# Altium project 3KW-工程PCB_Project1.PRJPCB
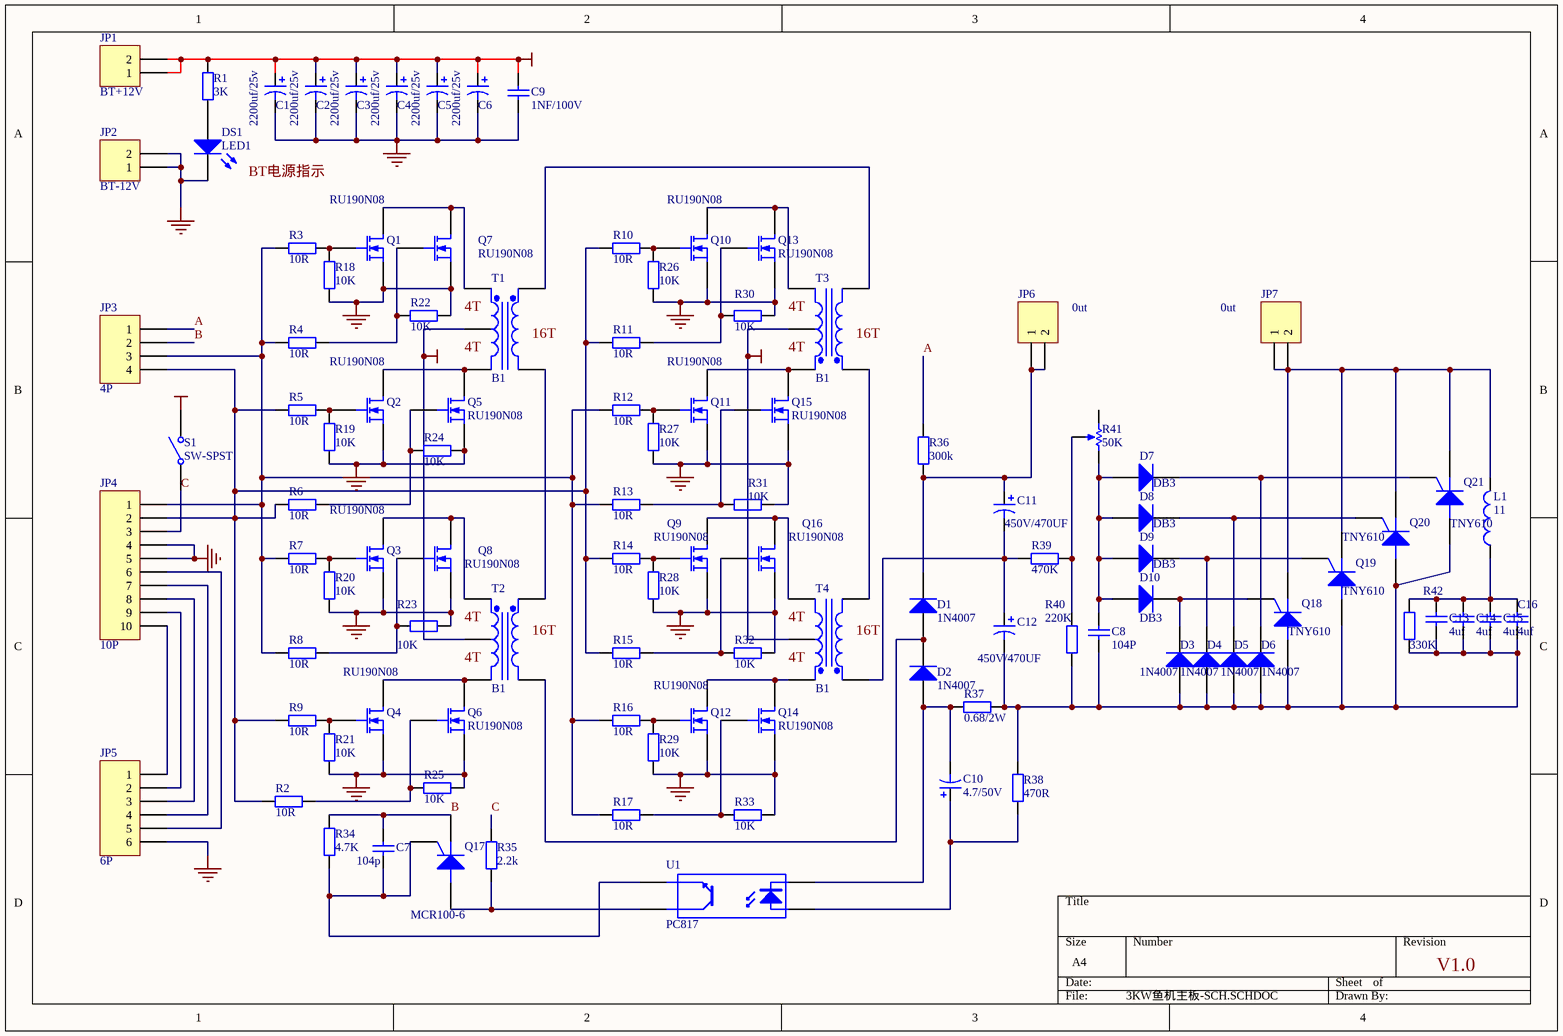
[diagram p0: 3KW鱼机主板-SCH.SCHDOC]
1 sheet, 104 parts. Net scope: global (net labels, ports and power ports of the same name join across sheets).

## Sheet 3KW鱼机主板-SCH.SCHDOC
size A4

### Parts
C1  2200uf/25v  [CAPPR5-5X5]
C2  2200uf/25v  [CAPPR5-5X5]
C3  2200uf/25v  [CAPPR5-5X5]
C4  2200uf/25v  [CAPPR5-5X5]
C5  2200uf/25v  [CAPPR5-5X5]
C6  2200uf/25v  [CAPPR5-5X5]
C7  104p  [RAD-0.3]
C8  104P  [RAD-0.3]
C9  1NF/100V  [RAD-0.1]
C10  4.7/50V  [CD5]
C11  450V/470UF  [450V/470UF]
C12  450V/470UF  [450V/470UF]
C13  4uf  [450v/3.5uf]
C14  4uf  [450v/3.5uf]
C15  4uf  [450v/3.5uf]
C16  4uf  [450v/3.5uf]
D1  1N4007  [DIO10.46-5.3x2.8]
D2  1N4007  [DIO10.46-5.3x2.8]
D3  1N4007  [DIO10.46-5.3x2.8]
D4  1N4007  [DIO10.46-5.3x2.8]
D5  1N4007  [DIO10.46-5.3x2.8]
D6  1N4007  [DIO10.46-5.3x2.8]
D7  DB3  [DIO7.8-4.6x2]
D8  DB3  [DIO7.8-4.6x2]
D9  DB3  [DIO7.8-4.6x2]
D10  DB3  [DIO7.8-4.6x2]
DS1  LED1  [BAT-2]
JP1  BT+12V  [HDR1X2]
JP2  BT-12V  [HDR1X2]
JP3  4P  [HDR1X4]
JP4  10P  [HDR1X10]
JP5  6P  [HDR1X6]
JP6  0ut  [HDR1X2]
JP7  0ut  [HDR1X2]
L1  11  [EC40]
Q1  RU190N08  [TO-220X]
Q2  RU190N08  [TO-220X]
Q3  RU190N08  [TO-220X]
Q4  RU190N08  [TO-220X]
Q5  RU190N08  [TO-220X]
Q6  RU190N08  [TO-220X]
Q7  RU190N08  [TO-220X]
Q8  RU190N08  [TO-220X]
Q9  RU190N08  [TO-220X]
Q10  RU190N08  [TO-220X]
Q11  RU190N08  [TO-220X]
Q12  RU190N08  [TO-220X]
Q13  RU190N08  [TO-220X]
Q14  RU190N08  [TO-220X]
Q15  RU190N08  [TO-220X]
Q16  RU190N08  [TO-220X]
Q17  MCR100-6  [BCY-W3/E4]
Q18  TNY610  [SFM-T3/E10.7V]
Q19  TNY610  [SFM-T3/E10.7V]
Q20  TNY610  [SFM-T3/E10.7V]
Q21  TNY610  [SFM-T3/E10.7V]
R1  3K  [AXIAL-0.4]
R2  10R  [AXIAL-0.4]
R3  10R  [AXIAL-0.4]
R4  10R  [AXIAL-0.4]
R5  10R  [AXIAL-0.4]
R6  10R  [AXIAL-0.4]
R7  10R  [AXIAL-0.4]
R8  10R  [AXIAL-0.4]
R9  10R  [AXIAL-0.4]
R10  10R  [AXIAL-0.4]
R11  10R  [AXIAL-0.4]
R12  10R  [AXIAL-0.4]
R13  10R  [AXIAL-0.4]
R14  10R  [AXIAL-0.4]
R15  10R  [AXIAL-0.4]
R16  10R  [AXIAL-0.4]
R17  10R  [AXIAL-0.4]
R18  10K  [AXIAL-0.4]
R19  10K  [AXIAL-0.4]
R20  10K  [AXIAL-0.4]
R21  10K  [AXIAL-0.4]
R22  10K  [AXIAL-0.4]
R23  10K  [AXIAL-0.4]
R24  10K  [AXIAL-0.4]
R25  10K  [AXIAL-0.4]
R26  10K  [AXIAL-0.4]
R27  10K  [AXIAL-0.4]
R28  10K  [AXIAL-0.4]
R29  10K  [AXIAL-0.4]
R30  10K  [AXIAL-0.4]
R31  10K  [AXIAL-0.4]
R32  10K  [AXIAL-0.4]
R33  10K  [AXIAL-0.4]
R34  4.7K  [AXIAL-0.4]
R35  2.2k  [AXIAL-0.4]
R36  300k  [AXIAL-0.4]
R37  0.68/2W  [AXIAL-0.4]
R38  470R  [AXIAL-0.4]
R39  470K  [AXIAL-0.4]
R40  220K  [AXIAL-0.4]
R41  50K  [VR5]
R42  330K  [AXIAL-0.5]
S1  SW-SPST  [SPST-2]
T1  B1  [EC40]
T2  B1  [EC40]
T3  B1  [EC40]
T4  B1  [EC40]
U1  PC817  [DIP-4]

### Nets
+12V: C1.1 C2.1 C3.1 C4.1 C5.1 C6.1 C9.2 JP1.1 JP1.2 R1.2 S1.2(NO) T1.4(SecCT) T2.4(SecCT) T3.4(SecCT) T4.4(SecCT)
GND: C1.2 C2.2 C3.2 C4.2 C5.2 C6.2 C9.1 DS1.2(K) JP2.1 JP2.2 JP4.4 JP4.5 JP5.6 Q1.3(S) Q2.3(S) Q3.3(S) Q4.3(S) Q5.3(S) Q6.3(S) Q7.3(S) Q8.3(S) Q9.3(S) Q10.3(S) Q11.3(S) Q12.3(S) Q13.3(S) Q14.3(S) Q15.3(S) Q16.3(S) R18.1 R19.1 R20.1 R21.1 R22.2 R23.2 R24.2 R25.2 R26.1 R27.1 R28.1 R29.1 R30.2 R31.2 R32.2 R33.2
A: JP3.1 R36.2
B: C7.1 JP3.2 Q17.3(K) R34.1
C: JP4.3 R35.1 S1.1(COMMON)
NetC7_2: C7.2 Q17.2(G) R34.2 U1.4(E)
NetC8_1: C8.1 C12.2 C13.1 C14.1 C15.1 C16.1 D3.1(A) D4.1(A) D5.1(A) D6.1(A) Q18.1(A) Q19.1(A) Q20.1(A) Q21.1(A) R37.2 R38.2 R40.1 R42.1
NetC8_2: C8.2 D7.1(A) D8.1(A) D9.1(A) D10.1(A) R41.2(BOT)
NetC10_1: C10.1 R38.1 U1.1(A)
NetC10_2: C10.2 D2.1(A) R37.1 U1.2(K)
NetC11_1: C11.1 D1.2(K) JP6.1 JP6.2 R36.1
NetC11_2: C11.2 C12.1 R39.1 T4.1(Pri+)
NetC13_2: C13.2 C14.2 C15.2 C16.2 L1.1 R42.2
NetD1_1: D1.1(A) D2.2(K) T2.2(Pri-)
NetD3_2: D3.2(K) D10.2(K) Q18.2(G)
NetD4_2: D4.2(K) D9.2(K) Q19.2(G)
NetD5_2: D5.2(K) D8.2(K) Q20.2(G)
NetD6_2: D6.2(K) D7.2(K) Q21.2(G)
NetDS1_1: DS1.1(A) R1.1
NetJP3_3: JP3.3 JP4.1 R3.1 R4.1 R7.1 R8.1 R12.1 R13.1 R16.1 R17.1
NetJP3_4: JP3.4 JP4.2 R2.1 R5.1 R6.1 R9.1 R10.1 R11.1 R14.1 R15.1
NetJP4_6: JP4.6 JP5.5
NetJP4_7: JP4.7 JP5.4
NetJP4_8: JP4.8 JP5.3
NetJP4_9: JP4.9 JP5.2
NetJP4_10: JP4.10 JP5.1
NetJP7_1: JP7.1 JP7.2 L1.2 Q18.3(K) Q19.3(K) Q20.3(K) Q21.3(K)
NetQ1_1: Q1.1(D) Q7.1(D) T1.3(Sec+)
NetQ1_2: Q1.2(G) R3.2 R18.2
NetQ2_1: Q2.1(D) Q5.1(D) T1.5(Sec-)
NetQ2_2: Q2.2(G) R5.2 R19.2
NetQ3_1: Q3.1(D) Q8.1(D) T2.3(Sec+)
NetQ3_2: Q3.2(G) R7.2 R20.2
NetQ4_1: Q4.1(D) Q6.1(D) T2.5(Sec-)
NetQ4_2: Q4.2(G) R9.2 R21.2
NetQ5_2: Q5.2(G) R6.2 R24.1
NetQ6_2: Q6.2(G) R2.2 R25.1
NetQ7_2: Q7.2(G) R4.2 R22.1
NetQ8_2: Q8.2(G) R8.2 R23.1
NetQ9_1: Q9.1(D) Q16.1(D) T4.5(Sec-)
NetQ9_2: Q9.2(G) R14.2 R28.2
NetQ10_1: Q10.1(D) Q13.1(D) T3.5(Sec-)
NetQ10_2: Q10.2(G) R10.2 R26.2
NetQ11_1: Q11.1(D) Q15.1(D) T3.3(Sec+)
NetQ11_2: Q11.2(G) R12.2 R27.2
NetQ12_1: Q12.1(D) Q14.1(D) T4.3(Sec+)
NetQ12_2: Q12.2(G) R16.2 R29.2
NetQ13_2: Q13.2(G) R11.2 R30.1
NetQ14_2: Q14.2(G) R17.2 R33.1
NetQ15_2: Q15.2(G) R13.2 R31.1
NetQ16_2: Q16.2(G) R15.2 R32.1
NetQ17_1: Q17.1(A) R35.2 U1.3(C)
NetR39_2: R39.2 R40.2 R41.3(TAP)
NetT1_1: T1.1(Pri+) T3.2(Pri-)
NetT1_2: T1.2(Pri-) T2.1(Pri+)
NetT3_1: T3.1(Pri+) T4.2(Pri-)

Not connected (* = marked no-connect by the designer): R41 1(TOP)

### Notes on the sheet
- BT电源指示
- (near T1) 4T
- (near T3) 4T
- (near T1) 16T
- (near T3) 16T
- (near T2) 4T
- (near T2) 16T
- (near T4) 4T
- (near T4) 16T
- V1.0

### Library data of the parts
C1-C6 C10-C12 = Cap Pol2: Polarized Capacitor (Axial); Value: 100pF
C7 C8 = Cap: Capacitor; Value: 104pF
C9 = Cap: Capacitor; Value: 100pF
C13-C16 = Cap: Capacitor
D1-D6 = Diode 1N4007: 1 Amp General Purpose Rectifier; Revision 1: 11-Jul-2000: SIM Model Added.; Revision 2: 17-Jul-2002: Re-released for DXP Platform.; Package Information: Latest Revision: Aug-1999; Code - JEDEC: DO-204-AL
D7-D10 = Diode: Default Diode; Code - JEDEC: DO-214-AB
DS1 = LED1: Typical RED GaAs LED
JP1 JP2 JP6 JP7 = Header 2: Header, 2-Pin
JP3 = Header 4: Header, 4-Pin
JP4 = Header 10: Header, 10-Pin
JP5 = Header 6: Header, 6-Pin
L1 = Inductor: Value: 10mH
Q1-Q16 = MOSFET-N: N-Channel MOSFET
Q17-Q21 = SCR: Silicon Controlled Rectifier; Code - JEDEC: TO-220-AB
R1-R16 R18-R34 R36 R37 R39 R40 = Res2: Resistor; Value: 1K
R17 R35 R42 = Res2: Resistor
R38 = Res2: Resistor; Value: 470K
R41 = RPot: Potentiometer; Set Position: 0.5; Value: 1K
S1 = SW-SPST: Single-Pole, Single-Throw Switch
T1-T4 = Trans CT Ideal: Center-Tapped Transformer (Ideal)
U1 = Optoisolator1: Optoisolator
